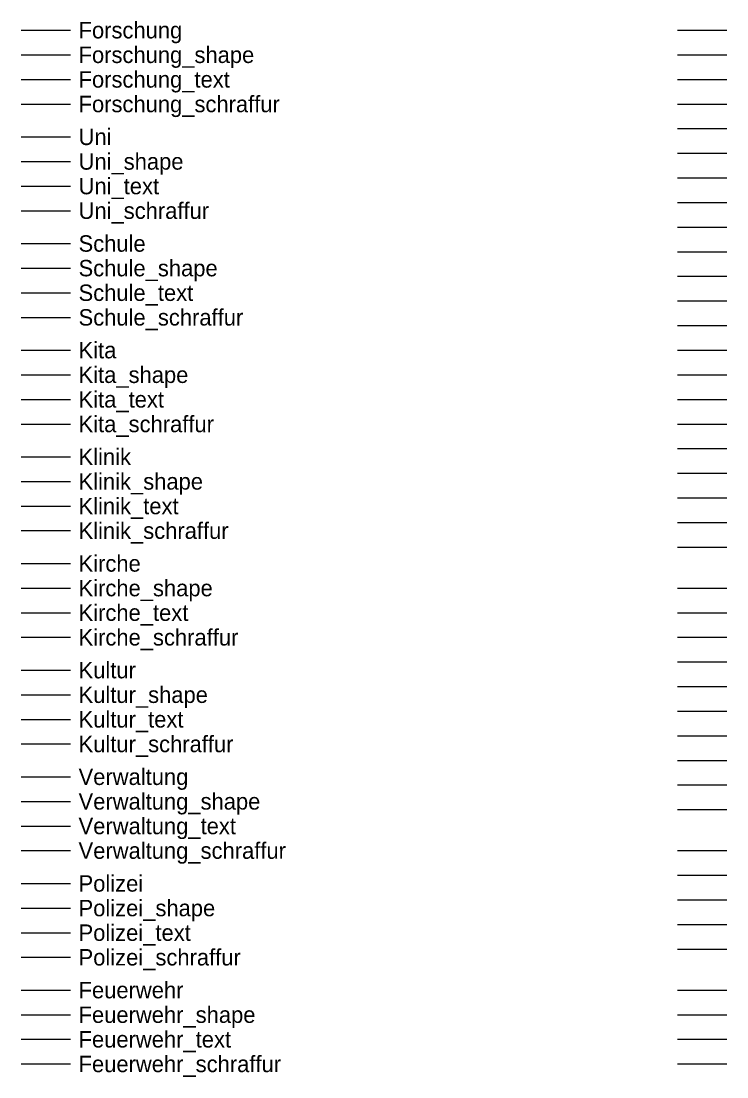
# Model space of a CAD drawing. Extents: x 0 to 177, y -135 to 1.
# Drawn here: x 0 to 43, y -63.8 to 0.6 of the extents above; entities that cross this region are included whole.
import ezdxf

# ---------------------------------------------------------------- set-up
doc = ezdxf.new("R2010")
doc.units = 0
for name, color, linetype in [('Baumscheibe', 7, 'Continuous'), ('Bef_flaeche_text', 7, 'Continuous'), ('Befestigte_Flaeche', 7, 'Continuous'), ('Bord_hoch', 7, 'Continuous'), ('Bord_tief', 7, 'Continuous'), ('Bruecke', 7, 'Continuous'), ('Container', 7, 'Continuous'), ('Deckschicht_linie', 7, 'Continuous'), ('Deckschicht_text', 7, 'Continuous'), ('Doppelschacht', 7, 'Continuous'), ('Eisba_gleisbett', 7, 'Continuous'), ('Eisba_gleise', 7, 'Continuous'), ('Eisba_kmstein', 7, 'Continuous'), ('Eisba_mast', 7, 'Continuous'), ('Eisba_signal', 7, 'Continuous'), ('Fahrscheinautomat', 7, 'Continuous'), ('Feuerwehr', 7, 'Continuous'), ('Feuerwehr_schraffur', 7, 'Continuous'), ('Feuerwehr_shape', 7, 'Continuous'), ('Feuerwehr_text', 7, 'Continuous'), ('Forschung', 7, 'Continuous'), ('Forschung_schraffur', 7, 'Continuous'), ('Forschung_shape', 7, 'Continuous'), ('Forschung_text', 7, 'Continuous'), ('Fundament', 7, 'Continuous'), ('Fundament_text', 7, 'Continuous'), ('Fussweg', 7, 'Continuous'), ('Haltestelle', 7, 'Continuous'), ('Haltestelle_Anzeige', 7, 'Continuous'), ('Kirche', 7, 'Continuous'), ('Kirche_schraffur', 7, 'Continuous'), ('Kirche_shape', 7, 'Continuous'), ('Kirche_text', 7, 'Continuous'), ('Kita', 7, 'Continuous'), ('Kita_schraffur', 7, 'Continuous'), ('Kita_shape', 7, 'Continuous'), ('Kita_text', 7, 'Continuous'), ('Klinik', 7, 'Continuous'), ('Klinik_schraffur', 7, 'Continuous'), ('Klinik_shape', 7, 'Continuous'), ('Klinik_text', 7, 'Continuous'), ('Kultur', 7, 'Continuous'), ('Kultur_schraffur', 7, 'Continuous'), ('Kultur_shape', 7, 'Continuous'), ('Kultur_text', 7, 'Continuous'), ('Leitplanke', 7, 'Continuous'), ('Parkautomat', 7, 'Continuous'), ('Parkplatz_linie', 7, 'Continuous'), ('Parkplatz_symbol', 7, 'Continuous'), ('Parkuhr', 7, 'Continuous'), ('Polizei', 7, 'Continuous'), ('Polizei_schraffur', 7, 'Continuous'), ('Polizei_shape', 7, 'Continuous'), ('Polizei_text', 7, 'Continuous'), ('Radweg', 7, 'Continuous'), ('Schacht_eckig', 7, 'Continuous'), ('Schacht_linie', 7, 'Continuous'), ('Schacht_rund', 7, 'Continuous'), ('Schallschutzwand', 7, 'Continuous'), ('Schule', 7, 'Continuous'), ('Schule_schraffur', 7, 'Continuous'), ('Schule_shape', 7, 'Continuous'), ('Schule_text', 7, 'Continuous'), ('Straba_gleisbett', 7, 'Continuous'), ('Straba_gleise', 7, 'Continuous'), ('Straba_mast', 7, 'Continuous'), ('Straba_schacht_88', 7, 'Continuous'), ('Straba_schacht_sonst', 7, 'Continuous'), ('Straba_signal', 7, 'Continuous'), ('Strassenmarkierung', 7, 'Continuous'), ('Tunnel', 7, 'Continuous'), ('Uni', 7, 'Continuous'), ('Uni_schraffur', 7, 'Continuous'), ('Uni_shape', 7, 'Continuous'), ('Uni_text', 7, 'Continuous'), ('Verwaltung', 7, 'Continuous'), ('Verwaltung_schraffur', 7, 'Continuous'), ('Verwaltung_shape', 7, 'Continuous'), ('Verwaltung_text', 7, 'Continuous'), ('Wartehaus', 7, 'Continuous'), ('Weg_unbef', 7, 'Continuous')]:
    doc.layers.add(name, color=color, linetype=linetype)

msp = doc.modelspace()

# ---------------------------------------------------------------- linework, layer by layer
at = {"layer": 'Baumscheibe'}
msp.add_line((40, -19.5), (43, -19.5), dxfattribs=at)
at = {"layer": 'Bef_flaeche_text'}
msp.add_line((40, -18), (43, -18), dxfattribs=at)
at = {"layer": 'Befestigte_Flaeche'}
msp.add_line((40, -16.5), (43, -16.5), dxfattribs=at)
at = {"layer": 'Bord_hoch'}
msp.add_line((40, -3), (43, -3), dxfattribs=at)
at = {"layer": 'Bord_tief'}
msp.add_line((40, -4.5), (43, -4.5), dxfattribs=at)
at = {"layer": 'Bruecke'}
msp.add_line((40, -30), (43, -30), dxfattribs=at)
at = {"layer": 'Container'}
msp.add_line((40, -28.5), (43, -28.5), dxfattribs=at)
at = {"layer": 'Deckschicht_linie'}
msp.add_line((40, -25.5), (43, -25.5), dxfattribs=at)
at = {"layer": 'Deckschicht_text'}
msp.add_line((40, -27), (43, -27), dxfattribs=at)
at = {"layer": 'Doppelschacht'}
msp.add_line((40, -61.5), (43, -61.5), dxfattribs=at)
at = {"layer": 'Eisba_gleisbett'}
msp.add_line((40, -51.5), (43, -51.5), dxfattribs=at)
at = {"layer": 'Eisba_gleise'}
msp.add_line((40, -50), (43, -50), dxfattribs=at)
at = {"layer": 'Eisba_kmstein'}
msp.add_line((40, -56), (43, -56), dxfattribs=at)
at = {"layer": 'Eisba_mast'}
msp.add_line((40, -53), (43, -53), dxfattribs=at)
at = {"layer": 'Eisba_signal'}
msp.add_line((40, -54.5), (43, -54.5), dxfattribs=at)
at = {"layer": 'Fahrscheinautomat'}
msp.add_line((40, -44.5), (43, -44.5), dxfattribs=at)
at = {"layer": 'Feuerwehr'}
msp.add_line((0, -58.5), (3, -58.5), dxfattribs=at)
at = {"layer": 'Feuerwehr_schraffur'}
msp.add_line((0, -63), (3, -63), dxfattribs=at)
at = {"layer": 'Feuerwehr_shape'}
msp.add_line((0, -60), (3, -60), dxfattribs=at)
at = {"layer": 'Feuerwehr_text'}
msp.add_line((0, -61.5), (3, -61.5), dxfattribs=at)
at = {"layer": 'Forschung'}
msp.add_line((0, 0), (3, 0), dxfattribs=at)
at = {"layer": 'Forschung_schraffur'}
msp.add_line((0, -4.5), (3, -4.5), dxfattribs=at)
at = {"layer": 'Forschung_shape'}
msp.add_line((0, -1.5), (3, -1.5), dxfattribs=at)
at = {"layer": 'Forschung_text'}
msp.add_line((0, -3), (3, -3), dxfattribs=at)
at = {"layer": 'Fundament'}
msp.add_line((40, -21), (43, -21), dxfattribs=at)
at = {"layer": 'Fundament_text'}
msp.add_line((40, -22.5), (43, -22.5), dxfattribs=at)
at = {"layer": 'Fussweg'}
msp.add_line((40, -12), (43, -12), dxfattribs=at)
at = {"layer": 'Haltestelle'}
msp.add_line((40, -41.5), (43, -41.5), dxfattribs=at)
at = {"layer": 'Haltestelle_Anzeige'}
msp.add_line((40, -47.5), (43, -47.5), dxfattribs=at)
at = {"layer": 'Kirche'}
msp.add_line((0, -32.5), (3, -32.5), dxfattribs=at)
at = {"layer": 'Kirche_schraffur'}
msp.add_line((0, -37), (3, -37), dxfattribs=at)
at = {"layer": 'Kirche_shape'}
msp.add_line((0, -34), (3, -34), dxfattribs=at)
at = {"layer": 'Kirche_text'}
msp.add_line((0, -35.5), (3, -35.5), dxfattribs=at)
at = {"layer": 'Kita'}
msp.add_line((0, -19.5), (3, -19.5), dxfattribs=at)
at = {"layer": 'Kita_schraffur'}
msp.add_line((0, -24), (3, -24), dxfattribs=at)
at = {"layer": 'Kita_shape'}
msp.add_line((0, -21), (3, -21), dxfattribs=at)
at = {"layer": 'Kita_text'}
msp.add_line((0, -22.5), (3, -22.5), dxfattribs=at)
at = {"layer": 'Klinik'}
msp.add_line((0, -26), (3, -26), dxfattribs=at)
at = {"layer": 'Klinik_schraffur'}
msp.add_line((0, -30.5), (3, -30.5), dxfattribs=at)
at = {"layer": 'Klinik_shape'}
msp.add_line((0, -27.5), (3, -27.5), dxfattribs=at)
at = {"layer": 'Klinik_text'}
msp.add_line((0, -29), (3, -29), dxfattribs=at)
at = {"layer": 'Kultur'}
msp.add_line((0, -39), (3, -39), dxfattribs=at)
at = {"layer": 'Kultur_schraffur'}
msp.add_line((0, -43.5), (3, -43.5), dxfattribs=at)
at = {"layer": 'Kultur_shape'}
msp.add_line((0, -40.5), (3, -40.5), dxfattribs=at)
at = {"layer": 'Kultur_text'}
msp.add_line((0, -42), (3, -42), dxfattribs=at)
at = {"layer": 'Leitplanke'}
msp.add_line((40, 0), (43, 0), dxfattribs=at)
at = {"layer": 'Parkautomat'}
msp.add_line((40, -9), (43, -9), dxfattribs=at)
at = {"layer": 'Parkplatz_linie'}
msp.add_line((40, -6), (43, -6), dxfattribs=at)
at = {"layer": 'Parkplatz_symbol'}
msp.add_line((40, -7.5), (43, -7.5), dxfattribs=at)
at = {"layer": 'Parkuhr'}
msp.add_line((40, -10.5), (43, -10.5), dxfattribs=at)
at = {"layer": 'Polizei'}
msp.add_line((0, -52), (3, -52), dxfattribs=at)
at = {"layer": 'Polizei_schraffur'}
msp.add_line((0, -56.5), (3, -56.5), dxfattribs=at)
at = {"layer": 'Polizei_shape'}
msp.add_line((0, -53.5), (3, -53.5), dxfattribs=at)
at = {"layer": 'Polizei_text'}
msp.add_line((0, -55), (3, -55), dxfattribs=at)
at = {"layer": 'Radweg'}
msp.add_line((40, -13.5), (43, -13.5), dxfattribs=at)
at = {"layer": 'Schacht_eckig'}
msp.add_line((40, -60), (43, -60), dxfattribs=at)
at = {"layer": 'Schacht_linie'}
msp.add_line((40, -63), (43, -63), dxfattribs=at)
at = {"layer": 'Schacht_rund'}
msp.add_line((40, -58.5), (43, -58.5), dxfattribs=at)
at = {"layer": 'Schallschutzwand'}
msp.add_line((40, -1.5), (43, -1.5), dxfattribs=at)
at = {"layer": 'Schule'}
msp.add_line((0, -13), (3, -13), dxfattribs=at)
at = {"layer": 'Schule_schraffur'}
msp.add_line((0, -17.5), (3, -17.5), dxfattribs=at)
at = {"layer": 'Schule_shape'}
msp.add_line((0, -14.5), (3, -14.5), dxfattribs=at)
at = {"layer": 'Schule_text'}
msp.add_line((0, -16), (3, -16), dxfattribs=at)
at = {"layer": 'Straba_gleisbett'}
msp.add_line((40, -46), (43, -46), dxfattribs=at)
at = {"layer": 'Straba_gleise'}
msp.add_line((40, -34), (43, -34), dxfattribs=at)
at = {"layer": 'Straba_mast'}
msp.add_line((40, -38.5), (43, -38.5), dxfattribs=at)
at = {"layer": 'Straba_schacht_88'}
msp.add_line((40, -35.5), (43, -35.5), dxfattribs=at)
at = {"layer": 'Straba_schacht_sonst'}
msp.add_line((40, -37), (43, -37), dxfattribs=at)
at = {"layer": 'Straba_signal'}
msp.add_line((40, -40), (43, -40), dxfattribs=at)
at = {"layer": 'Strassenmarkierung'}
msp.add_line((40, -24), (43, -24), dxfattribs=at)
at = {"layer": 'Tunnel'}
msp.add_line((40, -31.5), (43, -31.5), dxfattribs=at)
at = {"layer": 'Uni'}
msp.add_line((0, -6.5), (3, -6.5), dxfattribs=at)
at = {"layer": 'Uni_schraffur'}
msp.add_line((0, -11), (3, -11), dxfattribs=at)
at = {"layer": 'Uni_shape'}
msp.add_line((0, -8), (3, -8), dxfattribs=at)
at = {"layer": 'Uni_text'}
msp.add_line((0, -9.5), (3, -9.5), dxfattribs=at)
at = {"layer": 'Verwaltung'}
msp.add_line((0, -45.5), (3, -45.5), dxfattribs=at)
at = {"layer": 'Verwaltung_schraffur'}
msp.add_line((0, -50), (3, -50), dxfattribs=at)
at = {"layer": 'Verwaltung_shape'}
msp.add_line((0, -47), (3, -47), dxfattribs=at)
at = {"layer": 'Verwaltung_text'}
msp.add_line((0, -48.5), (3, -48.5), dxfattribs=at)
at = {"layer": 'Wartehaus'}
msp.add_line((40, -43), (43, -43), dxfattribs=at)
at = {"layer": 'Weg_unbef'}
msp.add_line((40, -15), (43, -15), dxfattribs=at)

# ---------------------------------------------------------------- texts
at = {"layer": 'Feuerwehr'}
msp.add_text('Feuerwehr', height=1, dxfattribs=at).set_placement((3.5, -59))
at = {"layer": 'Feuerwehr_schraffur'}
msp.add_text('Feuerwehr_schraffur', height=1, dxfattribs=at).set_placement((3.5, -63.5))
at = {"layer": 'Feuerwehr_shape'}
msp.add_text('Feuerwehr_shape', height=1, dxfattribs=at).set_placement((3.5, -60.5))
at = {"layer": 'Feuerwehr_text'}
msp.add_text('Feuerwehr_text', height=1, dxfattribs=at).set_placement((3.5, -62))
at = {"layer": 'Forschung'}
msp.add_text('Forschung', height=1, dxfattribs=at).set_placement((3.5, -0.5))
at = {"layer": 'Forschung_schraffur'}
msp.add_text('Forschung_schraffur', height=1, dxfattribs=at).set_placement((3.5, -5))
at = {"layer": 'Forschung_shape'}
msp.add_text('Forschung_shape', height=1, dxfattribs=at).set_placement((3.5, -2))
at = {"layer": 'Forschung_text'}
msp.add_text('Forschung_text', height=1, dxfattribs=at).set_placement((3.5, -3.5))
at = {"layer": 'Kirche'}
msp.add_text('Kirche', height=1, dxfattribs=at).set_placement((3.5, -33))
at = {"layer": 'Kirche_schraffur'}
msp.add_text('Kirche_schraffur', height=1, dxfattribs=at).set_placement((3.5, -37.5))
at = {"layer": 'Kirche_shape'}
msp.add_text('Kirche_shape', height=1, dxfattribs=at).set_placement((3.5, -34.5))
at = {"layer": 'Kirche_text'}
msp.add_text('Kirche_text', height=1, dxfattribs=at).set_placement((3.5, -36))
at = {"layer": 'Kita'}
msp.add_text('Kita', height=1, dxfattribs=at).set_placement((3.5, -20))
at = {"layer": 'Kita_schraffur'}
msp.add_text('Kita_schraffur', height=1, dxfattribs=at).set_placement((3.5, -24.5))
at = {"layer": 'Kita_shape'}
msp.add_text('Kita_shape', height=1, dxfattribs=at).set_placement((3.5, -21.5))
at = {"layer": 'Kita_text'}
msp.add_text('Kita_text', height=1, dxfattribs=at).set_placement((3.5, -23))
at = {"layer": 'Klinik'}
msp.add_text('Klinik', height=1, dxfattribs=at).set_placement((3.5, -26.5))
at = {"layer": 'Klinik_schraffur'}
msp.add_text('Klinik_schraffur', height=1, dxfattribs=at).set_placement((3.5, -31))
at = {"layer": 'Klinik_shape'}
msp.add_text('Klinik_shape', height=1, dxfattribs=at).set_placement((3.5, -28))
at = {"layer": 'Klinik_text'}
msp.add_text('Klinik_text', height=1, dxfattribs=at).set_placement((3.5, -29.5))
at = {"layer": 'Kultur'}
msp.add_text('Kultur', height=1, dxfattribs=at).set_placement((3.5, -39.5))
at = {"layer": 'Kultur_schraffur'}
msp.add_text('Kultur_schraffur', height=1, dxfattribs=at).set_placement((3.5, -44))
at = {"layer": 'Kultur_shape'}
msp.add_text('Kultur_shape', height=1, dxfattribs=at).set_placement((3.5, -41))
at = {"layer": 'Kultur_text'}
msp.add_text('Kultur_text', height=1, dxfattribs=at).set_placement((3.5, -42.5))
at = {"layer": 'Polizei'}
msp.add_text('Polizei', height=1, dxfattribs=at).set_placement((3.5, -52.5))
at = {"layer": 'Polizei_schraffur'}
msp.add_text('Polizei_schraffur', height=1, dxfattribs=at).set_placement((3.5, -57))
at = {"layer": 'Polizei_shape'}
msp.add_text('Polizei_shape', height=1, dxfattribs=at).set_placement((3.5, -54))
at = {"layer": 'Polizei_text'}
msp.add_text('Polizei_text', height=1, dxfattribs=at).set_placement((3.5, -55.5))
at = {"layer": 'Schule'}
msp.add_text('Schule', height=1, dxfattribs=at).set_placement((3.5, -13.5))
at = {"layer": 'Schule_schraffur'}
msp.add_text('Schule_schraffur', height=1, dxfattribs=at).set_placement((3.5, -18))
at = {"layer": 'Schule_shape'}
msp.add_text('Schule_shape', height=1, dxfattribs=at).set_placement((3.5, -15))
at = {"layer": 'Schule_text'}
msp.add_text('Schule_text', height=1, dxfattribs=at).set_placement((3.5, -16.5))
at = {"layer": 'Uni'}
msp.add_text('Uni', height=1, dxfattribs=at).set_placement((3.5, -7))
at = {"layer": 'Uni_schraffur'}
msp.add_text('Uni_schraffur', height=1, dxfattribs=at).set_placement((3.5, -11.5))
at = {"layer": 'Uni_shape'}
msp.add_text('Uni_shape', height=1, dxfattribs=at).set_placement((3.5, -8.5))
at = {"layer": 'Uni_text'}
msp.add_text('Uni_text', height=1, dxfattribs=at).set_placement((3.5, -10))
at = {"layer": 'Verwaltung'}
msp.add_text('Verwaltung', height=1, dxfattribs=at).set_placement((3.5, -46))
at = {"layer": 'Verwaltung_schraffur'}
msp.add_text('Verwaltung_schraffur', height=1, dxfattribs=at).set_placement((3.5, -50.5))
at = {"layer": 'Verwaltung_shape'}
msp.add_text('Verwaltung_shape', height=1, dxfattribs=at).set_placement((3.5, -47.5))
at = {"layer": 'Verwaltung_text'}
msp.add_text('Verwaltung_text', height=1, dxfattribs=at).set_placement((3.5, -49))

doc.saveas('drawing.dxf')
